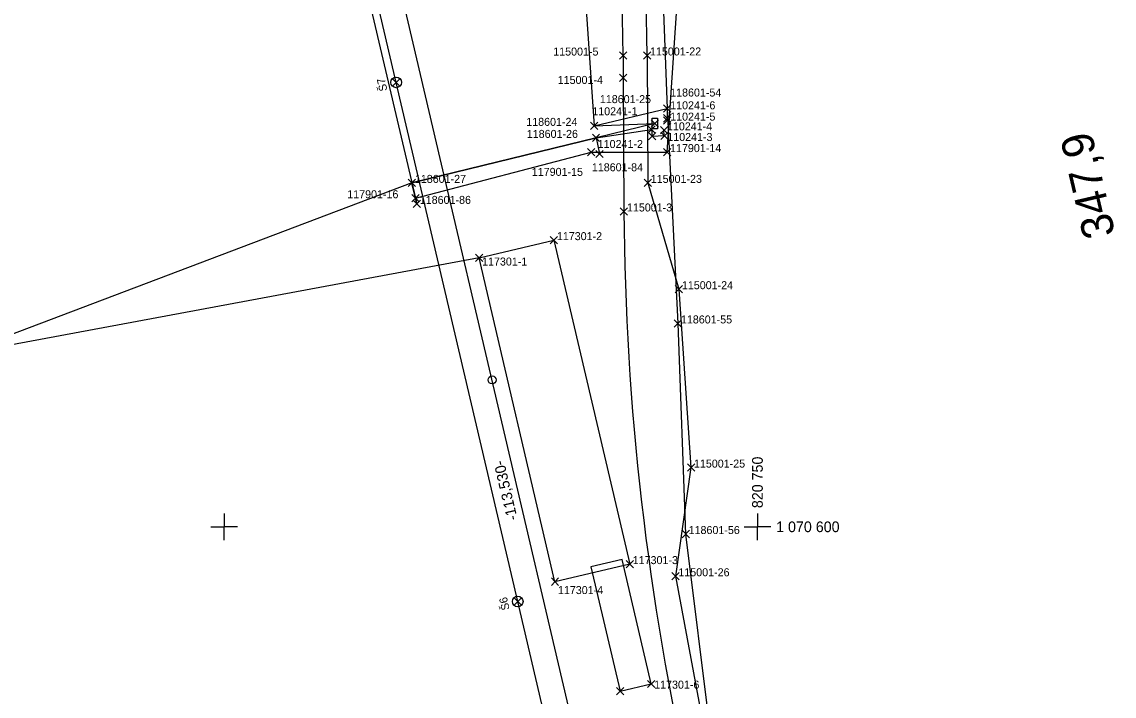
# Model space of a CAD drawing. Extents: x -821029 to -820632, y -1070881 to -1069931.
# Drawn here: x -820819 to -820716.6, y -1070615.9 to -1070552.6 of the extents above; entities that cross this region are included whole.
import ezdxf

# ---------------------------------------------------------------- set-up
doc = ezdxf.new("R2010")
doc.units = 0
for name, color, linetype in [('_PS_SO_číslo', 7, 'Continuous'), ('PS-11-02-31', 7, 'Continuous'), ('PS-11-02-41', 7, 'Continuous'), ('PS-11-02-92', 7, 'Continuous'), ('Sit', 7, 'Continuous'), ('SO-11-10-01', 7, 'Continuous'), ('SO-11-50-01', 7, 'Continuous'), ('SO-11-73-01', 7, 'Continuous'), ('SO-11-79-01', 7, 'Continuous'), ('SO-11-86-01', 7, 'Continuous'), ('Sttaniceni a namezniky', 7, 'Continuous'), ('VB_PS-11-02-41', 7, 'Continuous'), ('VB_SO-11-10-01', 7, 'Continuous'), ('VB_SO-11-50-01', 7, 'Continuous'), ('VB_SO-11-73-01', 7, 'Continuous'), ('VB_SO-11-79-01', 7, 'Continuous'), ('VB_SO-11-86-01', 7, 'Continuous')]:
    doc.layers.add(name, color=color, linetype=linetype)

msp = doc.modelspace()

# ---------------------------------------------------------------- linework, layer by layer
at = {"layer": '_PS_SO_číslo'}
for p, q in [((-820782.39, -1070567.75), (-820823.5, -1070583.32)), ((-820776.09, -1070574.77), (-820826.54, -1070584.17))]:
    msp.add_line(p, q, dxfattribs=at)
at = {"layer": 'PS-11-02-31'}
msp.add_line((-820765.13, -1070563.53), (-820764.8, -1070565.04), dxfattribs=at)
for points in [[(-820959.28, -1070122.22), (-820934.84, -1070144.09), (-820933, -1070146.6), (-820925.15, -1070161.74), (-820918.63, -1070175.61), (-820911.37, -1070188.87), (-820902.58, -1070186.65), (-820896.69, -1070196.98), (-820870.46, -1070236.45), (-820846.57, -1070277.08), (-820842.6, -1070282.11), (-820813.47, -1070365.17), (-820809.8, -1070374.33), (-820792.8, -1070426.72), (-820792.34, -1070428.47), (-820790.08, -1070430.86), (-820788.92, -1070435.58), (-820780.39, -1070470.86), (-820770.55, -1070511.61), (-820767.89, -1070524.68), (-820765.3, -1070562.4), (-820759.61, -1070562.18)], [(-820765.13, -1070563.53), (-820759.93, -1070562.74), (-820759.88, -1070563.37), (-820758.73, -1070563.32), (-820758.76, -1070562.82)], [(-820765.13, -1070563.53), (-820782.39, -1070567.75), (-820781.93, -1070569.72), (-820782.39, -1070567.75)]]:
    msp.add_lwpolyline(points, dxfattribs=at)
msp.add_lwpolyline([(-820759.36, -1070561.68), (-820759.36, -1070562.68), (-820759.86, -1070562.68), (-820759.86, -1070561.68)], close=True, dxfattribs=at)
at = {"layer": 'PS-11-02-41'}
msp.add_line((-820765.13, -1070563.53), (-820764.8, -1070565.04), dxfattribs=at)
for points in [[(-820782.43, -1070424.35), (-820792.8, -1070426.72), (-820792.34, -1070428.47), (-820790.08, -1070430.86), (-820770.55, -1070511.61), (-820767.89, -1070524.68), (-820765.3, -1070562.4), (-820758.46, -1070560.77), (-820758.46, -1070561.69), (-820758.46, -1070561.91)], [(-820781.93, -1070569.72), (-820782.39, -1070567.75), (-820765.13, -1070563.53), (-820759.93, -1070562.74), (-820759.88, -1070563.37), (-820758.73, -1070563.32), (-820758.76, -1070562.82)]]:
    msp.add_lwpolyline(points, dxfattribs=at)
at = {"layer": 'PS-11-02-92'}
msp.add_line((-820765.13, -1070563.53), (-820764.8, -1070565.04), dxfattribs=at)
for points in [[(-820782.43, -1070424.35), (-820792.8, -1070426.72), (-820792.34, -1070428.47), (-820790.08, -1070430.86), (-820770.55, -1070511.61), (-820767.89, -1070524.68), (-820765.3, -1070562.4), (-820758.46, -1070560.77), (-820758.46, -1070561.69), (-820758.46, -1070561.91)], [(-820781.93, -1070569.72), (-820782.39, -1070567.75), (-820765.13, -1070563.53), (-820759.93, -1070562.74), (-820759.88, -1070563.37), (-820758.73, -1070563.32), (-820758.76, -1070562.82)]]:
    msp.add_lwpolyline(points, dxfattribs=at)
at = {"layer": 'Sit'}
for p, q in [((-820800, -1070598.75), (-820800, -1070600)), ((-820750, -1070598.75), (-820750, -1070600)), ((-820801.25, -1070600), (-820800, -1070600)), ((-820798.75, -1070600), (-820800, -1070600)), ((-820800, -1070601.25), (-820800, -1070600)), ((-820751.25, -1070600), (-820750, -1070600)), ((-820748.75, -1070600), (-820750, -1070600)), ((-820750, -1070601.25), (-820750, -1070600))]:
    msp.add_line(p, q, dxfattribs=at)
at = {"layer": 'SO-11-10-01'}
for points in [[(-820761.02, -1070645.41), (-820786.89, -1070534.87), (-820787.46, -1070532.43), (-820788.03, -1070530), (-820808.6, -1070442.09), (-820809.13, -1070439.8), (-820809.67, -1070437.51), (-820820.71, -1070390.32)], [(-820717.05, -1070839.46), (-820726.3, -1070799.93), (-820741.68, -1070734.2), (-820752.33, -1070691), (-820761.08, -1070655.69), (-820772.47, -1070607.01), (-820783.86, -1070558.32), (-820795.25, -1070509.64), (-820806.65, -1070460.95), (-820811.32, -1070440.97)]]:
    msp.add_lwpolyline(points, dxfattribs=at)
for centre in [(-820783.86, -1070558.32), (-820772.47, -1070607.01)]:
    msp.add_circle(centre, 0.5, dxfattribs=at)
at = {"layer": 'SO-11-50-01'}
for points in [[(-820762.6, -1070555.81), (-820762.59, -1070557.9), (-820762.51, -1070570.43)], [(-820760.35, -1070555.8), (-820760.28, -1070567.75), (-820757.36, -1070577.72), (-820756.23, -1070594.45), (-820757.69, -1070604.64), (-820754.06, -1070624.09), (-820746.96, -1070655.19)]]:
    msp.add_lwpolyline(points, dxfattribs=at)
for centre, radius, start, end in [((-821012.54, -1070557.26), 249.95, 0.3326, 13.158), ((-821018.39, -1070557.95), 258.05, 0.4786, 13.012), ((-820512.52, -1070568.97), 250, 180.3346, 192.8532)]:
    msp.add_arc(centre, radius, start, end, dxfattribs=at)
at = {"layer": 'SO-11-73-01'}
for points in [[(-820776.09, -1070574.77), (-820769.08, -1070573.12), (-820761.97, -1070603.5), (-820768.98, -1070605.15)], [(-820762.88, -1070615.43), (-820759.96, -1070614.74), (-820762.69, -1070603.06), (-820765.61, -1070603.74)]]:
    msp.add_lwpolyline(points, close=True, dxfattribs=at)
at = {"layer": 'SO-11-79-01'}
msp.add_lwpolyline([(-820823.93, -1070391.03), (-820782.06, -1070569.19), (-820765.59, -1070564.86), (-820758.47, -1070564.86), (-820756.27, -1070532.22), (-820761.04, -1070511.48), (-820774.1, -1070459)], dxfattribs=at)
at = {"layer": 'SO-11-86-01'}
msp.add_line((-820765.13, -1070563.53), (-820764.8, -1070565.04), dxfattribs=at)
for points in [[(-820870.46, -1070236.45), (-820846.57, -1070277.08), (-820842.6, -1070282.11), (-820813.47, -1070365.17), (-820792.8, -1070426.72), (-820792.34, -1070428.47), (-820790.08, -1070430.86), (-820788.92, -1070435.58), (-820780.39, -1070470.86), (-820770.55, -1070511.61), (-820767.89, -1070524.68), (-820765.3, -1070562.4), (-820759.61, -1070562.18), (-820765.13, -1070563.53), (-820782.39, -1070567.76), (-820781.93, -1070569.72), (-820782.39, -1070567.76)], [(-820773.91, -1070463.73), (-820769.35, -1070482.63), (-820764.88, -1070502.04), (-820762.96, -1070509.81), (-820761.93, -1070514.25), (-820761.49, -1070521.75), (-820759.2, -1070540.95), (-820758.45, -1070560.77), (-820757.45, -1070580.93), (-820756.73, -1070600.68), (-820754.4, -1070619.51)]]:
    msp.add_lwpolyline(points, dxfattribs=at)
msp.add_lwpolyline([(-820759.36, -1070561.68), (-820759.36, -1070562.68), (-820759.86, -1070562.68), (-820759.86, -1070561.68)], close=True, dxfattribs=at)
at = {"layer": 'Sttaniceni a namezniky'}
msp.add_circle((-820774.87, -1070586.23), 0.375, dxfattribs=at)
at = {"layer": 'VB_PS-11-02-41'}
for p, q in [((-820758.8, -1070562.04), (-820758.11, -1070561.35)), ((-820758.11, -1070562.04), (-820758.8, -1070561.35)), ((-820758.8, -1070562.25), (-820758.11, -1070561.57)), ((-820758.11, -1070562.25), (-820758.8, -1070561.57)), ((-820760.28, -1070563.08), (-820759.59, -1070562.39)), ((-820759.59, -1070563.08), (-820760.28, -1070562.39)), ((-820760.22, -1070563.71), (-820759.53, -1070563.03)), ((-820759.53, -1070563.71), (-820760.22, -1070563.03)), ((-820759.1, -1070563.16), (-820758.41, -1070562.47)), ((-820758.41, -1070563.16), (-820759.1, -1070562.47)), ((-820759.07, -1070563.67), (-820758.38, -1070562.98)), ((-820758.38, -1070563.67), (-820759.07, -1070562.98))]:
    msp.add_line(p, q, dxfattribs=at)
at = {"layer": 'VB_SO-11-10-01'}
for p, q in [((-820784.21, -1070558.67), (-820783.52, -1070557.98)), ((-820783.52, -1070558.67), (-820784.21, -1070557.98)), ((-820772.81, -1070607.35), (-820772.13, -1070606.66)), ((-820772.13, -1070607.35), (-820772.81, -1070606.66))]:
    msp.add_line(p, q, dxfattribs=at)
at = {"layer": 'VB_SO-11-50-01'}
for p, q in [((-820762.94, -1070556.15), (-820762.25, -1070555.47)), ((-820762.25, -1070556.15), (-820762.94, -1070555.47)), ((-820760.69, -1070556.14), (-820760, -1070555.45)), ((-820760, -1070556.14), (-820760.69, -1070555.45)), ((-820762.93, -1070558.25), (-820762.24, -1070557.56)), ((-820762.24, -1070558.25), (-820762.93, -1070557.56)), ((-820760.62, -1070568.1), (-820759.93, -1070567.41)), ((-820759.93, -1070568.1), (-820760.62, -1070567.41)), ((-820762.86, -1070570.78), (-820762.17, -1070570.09)), ((-820762.17, -1070570.78), (-820762.86, -1070570.09)), ((-820757.7, -1070578.07), (-820757.02, -1070577.38)), ((-820757.02, -1070578.07), (-820757.7, -1070577.38)), ((-820756.57, -1070594.79), (-820755.88, -1070594.11)), ((-820755.88, -1070594.79), (-820756.57, -1070594.11)), ((-820758.03, -1070604.98), (-820757.34, -1070604.29)), ((-820757.34, -1070604.98), (-820758.03, -1070604.29))]:
    msp.add_line(p, q, dxfattribs=at)
at = {"layer": 'VB_SO-11-73-01'}
for p, q in [((-820769.42, -1070573.47), (-820768.74, -1070572.78)), ((-820768.74, -1070573.47), (-820769.42, -1070572.78)), ((-820776.43, -1070575.11), (-820775.75, -1070574.42)), ((-820775.75, -1070575.11), (-820776.43, -1070574.42)), ((-820762.31, -1070603.85), (-820761.62, -1070603.16)), ((-820761.62, -1070603.85), (-820762.31, -1070603.16)), ((-820769.32, -1070605.49), (-820768.64, -1070604.8)), ((-820768.64, -1070605.49), (-820769.32, -1070604.8)), ((-820760.3, -1070615.08), (-820759.61, -1070614.4)), ((-820759.61, -1070615.08), (-820760.3, -1070614.4)), ((-820763.22, -1070615.77), (-820762.53, -1070615.08)), ((-820762.53, -1070615.77), (-820763.22, -1070615.08))]:
    msp.add_line(p, q, dxfattribs=at)
at = {"layer": 'VB_SO-11-79-01'}
for p, q in [((-820765.94, -1070565.21), (-820765.25, -1070564.52)), ((-820765.25, -1070565.21), (-820765.94, -1070564.52)), ((-820758.81, -1070565.2), (-820758.13, -1070564.51)), ((-820758.13, -1070565.2), (-820758.81, -1070564.51)), ((-820782.41, -1070569.53), (-820781.72, -1070568.85)), ((-820781.72, -1070569.53), (-820782.41, -1070568.85))]:
    msp.add_line(p, q, dxfattribs=at)
at = {"layer": 'VB_SO-11-86-01'}
for p, q in [((-820758.8, -1070561.11), (-820758.11, -1070560.42)), ((-820758.11, -1070561.11), (-820758.8, -1070560.42)), ((-820765.64, -1070562.74), (-820764.95, -1070562.06)), ((-820764.95, -1070562.74), (-820765.64, -1070562.06)), ((-820759.95, -1070562.52), (-820759.27, -1070561.84)), ((-820759.27, -1070562.52), (-820759.95, -1070561.84)), ((-820765.47, -1070563.88), (-820764.79, -1070563.19)), ((-820764.79, -1070563.88), (-820765.47, -1070563.19)), ((-820765.14, -1070565.38), (-820764.46, -1070564.7)), ((-820764.46, -1070565.38), (-820765.14, -1070564.7)), ((-820782.73, -1070568.1), (-820782.04, -1070567.41)), ((-820782.04, -1070568.1), (-820782.73, -1070567.41)), ((-820782.27, -1070570.06), (-820781.58, -1070569.37)), ((-820781.58, -1070570.06), (-820782.27, -1070569.37)), ((-820757.8, -1070581.27), (-820757.11, -1070580.59)), ((-820757.11, -1070581.27), (-820757.8, -1070580.59)), ((-820757.07, -1070601.02), (-820756.38, -1070600.33)), ((-820756.38, -1070601.02), (-820757.07, -1070600.33))]:
    msp.add_line(p, q, dxfattribs=at)

# ---------------------------------------------------------------- texts
at = {"layer": 'Sit'}
msp.add_text('820 750', height=1, rotation=90, dxfattribs=at).set_placement((-820749.5, -1070598.25))
msp.add_text('1 070 600', height=1, dxfattribs=at).set_placement((-820748.25, -1070600.5))
at = {"layer": 'SO-11-10-01'}
msp.add_text('-113,530-', height=1, rotation=103.1701, dxfattribs=at).set_placement((-820772.47, -1070599.28))
at = {"layer": 'Sttaniceni a namezniky'}
msp.add_text('347,9', height=3, rotation=103.1701, dxfattribs=at).set_placement((-820716.44, -1070572.56))
at = {"layer": 'VB_PS-11-02-41'}
for s, p in [(' 110241-6', (-820758.46, -1070560.85)), (' 110241-1', (-820765.76, -1070561.41)), (' 110241-5', (-820758.46, -1070561.91)), (' 110241-4', (-820758.76, -1070562.82)), (' 110241-3', (-820758.73, -1070563.82)), (' 110241-2', (-820765.25, -1070564.48))]:
    msp.add_text(s, height=0.75, dxfattribs=at).set_placement(p)
at = {"layer": 'VB_SO-11-10-01'}
for s, p in [('Š7', (-820784.68, -1070559.06)), ('Š6', (-820773.22, -1070607.73))]:
    msp.add_text(s, height=0.75, rotation=103.1701, dxfattribs=at).set_placement(p)
at = {"layer": 'VB_SO-11-50-01'}
for s, p in [(' 115001-5', (-820769.42, -1070555.81)), (' 115001-22', (-820760.35, -1070555.8)), (' 115001-4', (-820769, -1070558.47)), (' 115001-23', (-820760.28, -1070567.75)), (' 115001-3', (-820762.51, -1070570.43)), (' 115001-24', (-820757.36, -1070577.72)), (' 115001-25', (-820756.23, -1070594.45)), (' 115001-26', (-820757.69, -1070604.64))]:
    msp.add_text(s, height=0.75, dxfattribs=at).set_placement(p)
at = {"layer": 'VB_SO-11-73-01'}
for s, p in [(' 117301-2', (-820769.08, -1070573.12)), (' 117301-1', (-820776.09, -1070575.5)), (' 117301-3', (-820761.97, -1070603.5)), (' 117301-4', (-820768.98, -1070606.31)), (' 117301-6', (-820759.96, -1070615.18))]:
    msp.add_text(s, height=0.75, dxfattribs=at).set_placement(p)
at = {"layer": 'VB_SO-11-79-01'}
for s, p in [(' 117901-14', (-820758.47, -1070564.86)), (' 117901-15', (-820771.43, -1070567.09)), (' 117901-16', (-820788.73, -1070569.19))]:
    msp.add_text(s, height=0.75, dxfattribs=at).set_placement(p)
at = {"layer": 'VB_SO-11-86-01'}
for s, p in [(' 118601-54', (-820758.46, -1070559.65)), (' 118601-25', (-820765.05, -1070560.27)), (' 118601-24', (-820771.95, -1070562.4)), (' 118601-26', (-820771.9, -1070563.53)), (' 118601-84', (-820765.8, -1070566.66)), (' 118601-27', (-820782.39, -1070567.75)), (' 118601-86', (-820781.93, -1070569.72)), (' 118601-55', (-820757.45, -1070580.93)), (' 118601-56', (-820756.73, -1070600.68))]:
    msp.add_text(s, height=0.75, dxfattribs=at).set_placement(p)

doc.saveas('drawing.dxf')
